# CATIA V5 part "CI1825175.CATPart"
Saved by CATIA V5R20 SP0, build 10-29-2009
Part number: CI1825175
Bounding box of the stored display mesh (mm): x -24 to 24, y -19.337 to 209.5, z -31.667 to 27.272
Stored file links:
  C:\Users\Raffaele\Desktop\3D X SITO CF\BOLEX\19-INCLINED ASSEMBLY REF_CI\CI1825175.CATPart

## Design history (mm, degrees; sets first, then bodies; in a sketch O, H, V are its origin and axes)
Set1
  DatumSurface1 to DatumSurface16 "MANIFOLD_SOLID_BREP #393"
  DatumSurface17 to DatumSurface39 "MANIFOLD_SOLID_BREP #1138"
Body1 (main body)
